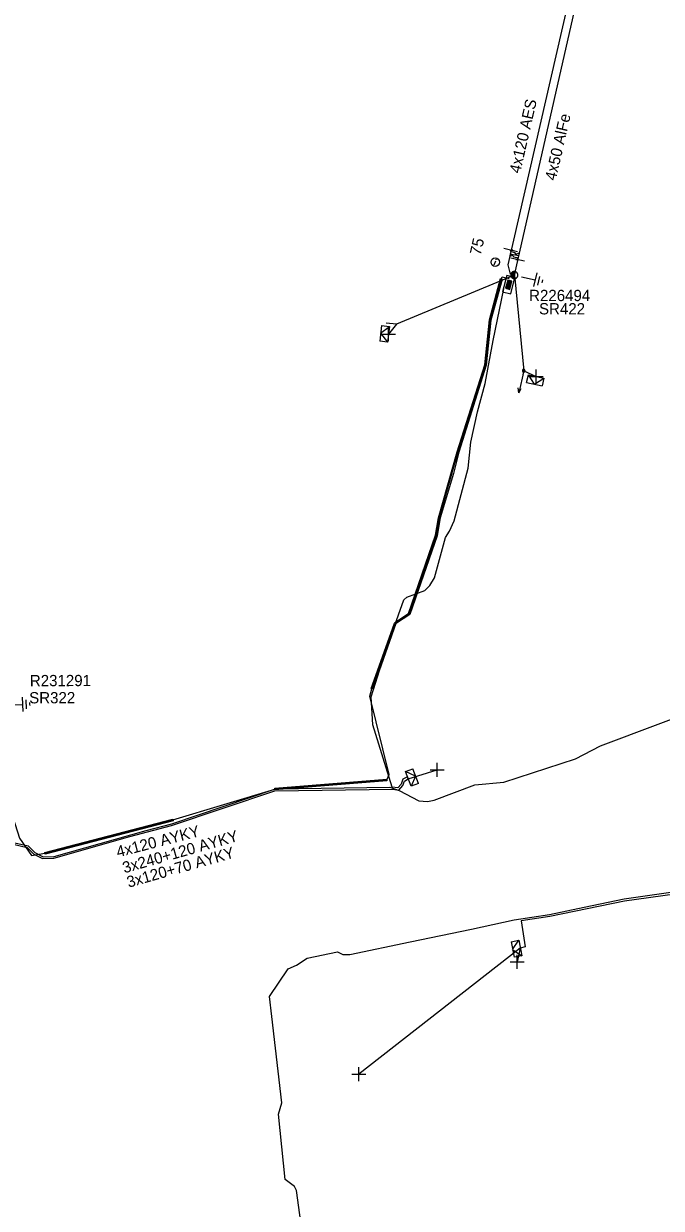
# Model space of a CAD drawing. Extents: x -544780 to -541582, y -1198995 to -1196551.
# Drawn here: x -542649.1 to -542592.5, y -1198255 to -1198149.8 of the extents above; entities that cross this region are included whole.
import ezdxf

# ---------------------------------------------------------------- set-up
doc = ezdxf.new("R2010")
doc.units = 0
for name, color, linetype in [('Vrstva 1', 7, 'Continuous'), ('Vrstva 10', 7, 'Continuous'), ('Vrstva 13', 7, 'Continuous'), ('Vrstva 14', 7, 'Continuous'), ('Vrstva 15', 7, 'Continuous'), ('Vrstva 18', 7, 'Continuous'), ('Vrstva 2', 7, 'Continuous'), ('Vrstva 20', 7, 'Continuous'), ('Vrstva 28', 7, 'Continuous'), ('Vrstva 29', 7, 'Continuous'), ('Vrstva 30', 7, 'Continuous'), ('Vrstva 31', 7, 'Continuous'), ('Vrstva 34', 7, 'Continuous'), ('Vrstva 36', 7, 'Continuous'), ('Vrstva 5', 7, 'Continuous'), ('Vrstva 50', 7, 'Continuous'), ('Vrstva 51', 7, 'Continuous'), ('Vrstva 54', 7, 'Continuous'), ('Vrstva 59', 7, 'Continuous'), ('Vrstva 6', 7, 'Continuous'), ('Vrstva 8', 7, 'Continuous'), ('Vrstva 9', 7, 'Continuous')]:
    doc.layers.add(name, color=color, linetype=linetype)

# ---------------------------------------------------------------- blocks, each defined once
blk = doc.blocks.new('NN440')
at = {"layer": 'Vrstva 2'}
for points in [[(0.63, 0), (0.63, 0.06), (0.62, 0.13), (0.6, 0.19), (0.58, 0.25), (0.55, 0.31), (0.51, 0.37), (0.47, 0.42), (0.42, 0.46), (0.37, 0.51), (0.32, 0.54), (0.26, 0.57), (0.2, 0.59), (0.13, 0.61), (0.07, 0.62), (0, 0.63), (-0.06, 0.62), (-0.13, 0.61), (-0.19, 0.59), (-0.26, 0.57), (-0.31, 0.54), (-0.37, 0.51), (-0.42, 0.46), (-0.47, 0.42), (-0.51, 0.37), (-0.54, 0.31), (-0.57, 0.25), (-0.6, 0.19), (-0.62, 0.13), (-0.63, 0.06), (-0.63, 0), (-0.63, -0.07), (-0.62, -0.14), (-0.6, -0.2), (-0.57, -0.26), (-0.54, -0.32), (-0.51, -0.37), (-0.47, -0.43), (-0.42, -0.47), (-0.37, -0.51), (-0.31, -0.55), (-0.26, -0.58), (-0.19, -0.6), (-0.13, -0.62), (-0.06, -0.63), (0, -0.63), (0.07, -0.63), (0.13, -0.62), (0.2, -0.6), (0.26, -0.58), (0.32, -0.55), (0.37, -0.51), (0.42, -0.47), (0.47, -0.43), (0.51, -0.37), (0.55, -0.32), (0.58, -0.26), (0.6, -0.2), (0.62, -0.14), (0.63, -0.07), (0.63, 0)], [(-0.63, 0), (0.63, 0)], [(-0.6, -0.18), (0.57, -0.18)], [(-0.51, -0.32), (0.5, -0.32)], [(-0.37, -0.47), (0.35, -0.47)]]:
    blk.add_lwpolyline(points, dxfattribs=at)
blk = doc.blocks.new('NN560')
at = {"layer": 'Vrstva 2'}
for points in [[(2, 0), (1.59, 0.14)], [(0, 0), (2, 0)], [(2, 0), (1.59, -0.13)]]:
    blk.add_lwpolyline(points, dxfattribs=at)
blk = doc.blocks.new('NN840')
at = {"layer": 'Vrstva 15'}
for points in [[(0, 0.62), (0, -0.63)], [(-0.75, -0.71), (-0.75, -0.66)], [(-0.73, -0.76), (-0.75, -0.71)], [(-0.66, -0.8), (-0.73, -0.76)], [(-0.63, -0.8), (-0.66, -0.8)], [(-0.56, -0.76), (-0.63, -0.8)], [(-0.54, -0.71), (-0.56, -0.76)], [(-0.54, -0.38), (-0.54, -0.71)], [(-0.33, -0.38), (-0.33, -0.8)], [(-0.33, -0.64), (-0.13, -0.38)], [(-0.26, -0.56), (-0.09, -0.8)]]:
    blk.add_lwpolyline(points, dxfattribs=at)
blk = doc.blocks.new('NN770')
at = {"layer": 'Vrstva 10'}
for p, q in [((0, 0.19), (0, 0.26)), ((0, -0.28), (0, 0.11))]:
    blk.add_line(p, q, dxfattribs=at)
blk.add_circle((0, -0.01), 0.375, dxfattribs=at)
blk = doc.blocks.new('NN800')
at = {"layer": 'Vrstva 1'}
for points in [[(-0.44, 0.44), (0.44, -0.44)], [(-0.44, -0.44), (0.44, 0.44)]]:
    blk.add_lwpolyline(points, dxfattribs=at)
blk = doc.blocks.new('NN620')
at = {"layer": 'Vrstva 8'}
for points in [[(0.75, 0), (-0.75, 0)], [(-0.75, 0), (-0.75, -0.75)], [(0.75, -0.75), (0.75, 0)], [(-0.75, -0.75), (0.75, -0.75)], [(0.37, -0.18), (-0.38, -0.18)], [(-0.38, -0.18), (-0.38, -0.56)], [(-0.38, -0.56), (0.37, -0.56)], [(0.32, -0.23), (-0.33, -0.23)], [(-0.33, -0.23), (-0.33, -0.51)], [(-0.33, -0.51), (0.32, -0.51)], [(0.27, -0.27), (-0.28, -0.27)], [(-0.28, -0.27), (-0.28, -0.46)], [(-0.28, -0.46), (0.27, -0.46)], [(0.23, -0.32), (-0.23, -0.32)], [(-0.23, -0.32), (-0.23, -0.42)], [(-0.23, -0.42), (0.23, -0.42)], [(-0.19, -0.37), (0.19, -0.37)], [(0.23, -0.42), (0.23, -0.32)], [(0.27, -0.46), (0.27, -0.27)], [(0.32, -0.51), (0.32, -0.23)], [(0.37, -0.56), (0.37, -0.18)]]:
    blk.add_lwpolyline(points, dxfattribs=at)
blk = doc.blocks.new('NN630')
at = {"layer": 'Vrstva 9'}
for points in [[(0, -0.7), (-0.7, 0)], [(-0.7, -0.7), (-0.7, 0), (0.7, 0), (0.7, -0.7)], [(-0.7, -0.7), (0.7, -0.7)], [(0, -0.7), (0.7, 0)]]:
    blk.add_lwpolyline(points, dxfattribs=at)
blk = doc.blocks.new('NN810')
at = {"layer": 'Vrstva 14'}
for points in [[(0, -0.64), (0, -1.89)], [(0.63, -1.89), (-0.62, -1.89)], [(0.39, -2.2), (-0.4, -2.2)], [(0, -2.52), (-0.12, -2.52)], [(0.14, -2.52), (0, -2.52)]]:
    blk.add_lwpolyline(points, dxfattribs=at)
blk = doc.blocks.new('NN500')
at = {"layer": 'Vrstva 2'}
for points in [[(0, -0.24), (0.02, -0.23), (0.05, -0.23), (0.07, -0.22), (0.09, -0.22), (0.12, -0.2), (0.14, -0.19), (0.16, -0.18), (0.17, -0.16), (0.19, -0.14), (0.2, -0.12), (0.21, -0.1), (0.22, -0.07), (0.23, -0.05), (0.23, -0.02), (0.23, 0), (0.23, 0.02), (0.23, 0.05), (0.22, 0.07), (0.21, 0.1), (0.2, 0.12), (0.19, 0.14), (0.17, 0.16), (0.16, 0.17), (0.14, 0.19), (0.12, 0.2), (0.09, 0.21), (0.07, 0.22), (0.05, 0.23), (0.02, 0.23), (0, 0.23), (-0.03, 0.23), (-0.05, 0.23), (-0.07, 0.22), (-0.1, 0.21), (-0.12, 0.2), (-0.14, 0.19), (-0.16, 0.17), (-0.18, 0.16), (-0.19, 0.14), (-0.2, 0.12), (-0.22, 0.1), (-0.22, 0.07), (-0.23, 0.05), (-0.23, 0.02), (-0.24, 0), (-0.23, -0.02), (-0.23, -0.05), (-0.22, -0.07), (-0.22, -0.1), (-0.2, -0.12), (-0.19, -0.14), (-0.18, -0.16), (-0.16, -0.18), (-0.14, -0.19), (-0.12, -0.2), (-0.1, -0.22), (-0.07, -0.22), (-0.05, -0.23), (-0.03, -0.23), (0, -0.24)], [(0, -0.24), (0.02, -0.23), (0.05, -0.23), (0.07, -0.22), (0.09, -0.22), (0.12, -0.2), (0.14, -0.19), (0.16, -0.18), (0.17, -0.16), (0.19, -0.14), (0.2, -0.12), (0.21, -0.1), (0.22, -0.07), (0.23, -0.05), (0.23, -0.02), (0.23, 0), (0.23, 0.02), (0.23, 0.05), (0.22, 0.07), (0.21, 0.1), (0.2, 0.12), (0.19, 0.14), (0.17, 0.16), (0.16, 0.17), (0.14, 0.19), (0.12, 0.2), (0.09, 0.21), (0.07, 0.22), (0.05, 0.23), (0.02, 0.23), (0, 0.23), (-0.03, 0.23), (-0.05, 0.23), (-0.07, 0.22), (-0.1, 0.21), (-0.12, 0.2), (-0.14, 0.19), (-0.16, 0.17), (-0.18, 0.16), (-0.19, 0.14), (-0.2, 0.12), (-0.22, 0.1), (-0.22, 0.07), (-0.23, 0.05), (-0.23, 0.02), (-0.24, 0), (-0.23, -0.02), (-0.23, -0.05), (-0.22, -0.07), (-0.22, -0.1), (-0.2, -0.12), (-0.19, -0.14), (-0.18, -0.16), (-0.16, -0.18), (-0.14, -0.19), (-0.12, -0.2), (-0.1, -0.22), (-0.07, -0.22), (-0.05, -0.23), (-0.03, -0.23), (0, -0.24)], [(0, -0.21), (0.02, -0.2), (0.04, -0.2), (0.06, -0.2), (0.08, -0.19), (0.1, -0.18), (0.12, -0.17), (0.14, -0.15), (0.15, -0.14), (0.16, -0.12), (0.18, -0.1), (0.19, -0.08), (0.19, -0.06), (0.2, -0.04), (0.2, -0.02), (0.2, 0), (0.2, 0.02), (0.2, 0.04), (0.19, 0.06), (0.19, 0.08), (0.18, 0.1), (0.16, 0.12), (0.15, 0.14), (0.14, 0.15), (0.12, 0.17), (0.1, 0.18), (0.08, 0.19), (0.06, 0.19), (0.04, 0.2), (0.02, 0.2), (0, 0.2), (-0.02, 0.2), (-0.04, 0.2), (-0.06, 0.19), (-0.08, 0.19), (-0.1, 0.18), (-0.12, 0.17), (-0.14, 0.15), (-0.15, 0.14), (-0.17, 0.12), (-0.18, 0.1), (-0.19, 0.08), (-0.2, 0.06), (-0.2, 0.04), (-0.21, 0.02), (-0.21, 0), (-0.21, -0.02), (-0.2, -0.04), (-0.2, -0.06), (-0.19, -0.08), (-0.18, -0.1), (-0.17, -0.12), (-0.15, -0.14), (-0.14, -0.15), (-0.12, -0.17), (-0.1, -0.18), (-0.08, -0.19), (-0.06, -0.2), (-0.04, -0.2), (-0.02, -0.2), (0, -0.21)], [(0, -0.18), (0.02, -0.18), (0.04, -0.17), (0.05, -0.17), (0.07, -0.16), (0.09, -0.15), (0.1, -0.14), (0.12, -0.13), (0.13, -0.12), (0.14, -0.1), (0.15, -0.09), (0.16, -0.07), (0.17, -0.05), (0.17, -0.04), (0.17, -0.02), (0.17, 0), (0.17, 0.02), (0.17, 0.04), (0.17, 0.05), (0.16, 0.07), (0.15, 0.09), (0.14, 0.1), (0.13, 0.12), (0.12, 0.13), (0.1, 0.14), (0.09, 0.15), (0.07, 0.16), (0.05, 0.17), (0.04, 0.17), (0.02, 0.17), (0, 0.18), (-0.02, 0.17), (-0.04, 0.17), (-0.06, 0.17), (-0.07, 0.16), (-0.09, 0.15), (-0.1, 0.14), (-0.12, 0.13), (-0.13, 0.12), (-0.14, 0.1), (-0.15, 0.09), (-0.16, 0.07), (-0.17, 0.05), (-0.17, 0.04), (-0.18, 0.02), (-0.18, 0), (-0.18, -0.02), (-0.17, -0.04), (-0.17, -0.05), (-0.16, -0.07), (-0.15, -0.09), (-0.14, -0.1), (-0.13, -0.12), (-0.12, -0.13), (-0.1, -0.14), (-0.09, -0.15), (-0.07, -0.16), (-0.06, -0.17), (-0.04, -0.17), (-0.02, -0.18), (0, -0.18)], [(0, -0.15), (0.01, -0.15), (0.03, -0.14), (0.04, -0.14), (0.06, -0.13), (0.07, -0.13), (0.08, -0.12), (0.1, -0.11), (0.11, -0.1), (0.12, -0.09), (0.13, -0.07), (0.13, -0.06), (0.14, -0.05), (0.14, -0.03), (0.14, -0.02), (0.14, 0), (0.14, 0.01), (0.14, 0.03), (0.14, 0.04), (0.13, 0.06), (0.13, 0.07), (0.12, 0.09), (0.11, 0.1), (0.1, 0.11), (0.08, 0.12), (0.07, 0.13), (0.06, 0.13), (0.04, 0.14), (0.03, 0.14), (0.01, 0.14), (0, 0.15), (-0.02, 0.14), (-0.03, 0.14), (-0.05, 0.14), (-0.06, 0.13), (-0.07, 0.13), (-0.09, 0.12), (-0.1, 0.11), (-0.11, 0.1), (-0.12, 0.09), (-0.13, 0.07), (-0.13, 0.06), (-0.14, 0.04), (-0.14, 0.03), (-0.15, 0.01), (-0.15, 0), (-0.15, -0.02), (-0.14, -0.03), (-0.14, -0.05), (-0.13, -0.06), (-0.13, -0.07), (-0.12, -0.09), (-0.11, -0.1), (-0.1, -0.11), (-0.09, -0.12), (-0.07, -0.13), (-0.06, -0.13), (-0.05, -0.14), (-0.03, -0.14), (-0.02, -0.15), (0, -0.15)], [(0, -0.12), (0.01, -0.12), (0.02, -0.11), (0.03, -0.11), (0.05, -0.11), (0.06, -0.1), (0.07, -0.09), (0.08, -0.09), (0.09, -0.08), (0.09, -0.07), (0.1, -0.06), (0.11, -0.05), (0.11, -0.04), (0.11, -0.02), (0.11, -0.01), (0.12, 0), (0.11, 0.01), (0.11, 0.02), (0.11, 0.04), (0.11, 0.05), (0.1, 0.06), (0.09, 0.07), (0.09, 0.08), (0.08, 0.09), (0.07, 0.09), (0.06, 0.1), (0.05, 0.11), (0.03, 0.11), (0.02, 0.11), (0.01, 0.12), (0, 0.12), (-0.01, 0.12), (-0.03, 0.11), (-0.04, 0.11), (-0.05, 0.11), (-0.06, 0.1), (-0.07, 0.09), (-0.08, 0.09), (-0.09, 0.08), (-0.1, 0.07), (-0.1, 0.06), (-0.11, 0.05), (-0.11, 0.04), (-0.12, 0.02), (-0.12, 0.01), (-0.12, 0), (-0.12, -0.01), (-0.12, -0.02), (-0.11, -0.04), (-0.11, -0.05), (-0.1, -0.06), (-0.1, -0.07), (-0.09, -0.08), (-0.08, -0.09), (-0.07, -0.09), (-0.06, -0.1), (-0.05, -0.11), (-0.04, -0.11), (-0.03, -0.11), (-0.01, -0.12), (0, -0.12)], [(0, -0.09), (0.01, -0.09), (0.02, -0.09), (0.03, -0.08), (0.03, -0.08), (0.04, -0.08), (0.05, -0.07), (0.06, -0.07), (0.06, -0.06), (0.07, -0.05), (0.07, -0.04), (0.08, -0.04), (0.08, -0.03), (0.08, -0.02), (0.09, -0.01), (0.09, 0), (0.09, 0.01), (0.08, 0.02), (0.08, 0.03), (0.08, 0.03), (0.07, 0.04), (0.07, 0.05), (0.06, 0.06), (0.06, 0.06), (0.05, 0.07), (0.04, 0.07), (0.03, 0.08), (0.03, 0.08), (0.02, 0.08), (0.01, 0.09), (0, 0.09), (-0.01, 0.09), (-0.02, 0.08), (-0.03, 0.08), (-0.04, 0.08), (-0.04, 0.07), (-0.05, 0.07), (-0.06, 0.06), (-0.07, 0.06), (-0.07, 0.05), (-0.08, 0.04), (-0.08, 0.03), (-0.08, 0.03), (-0.09, 0.02), (-0.09, 0.01), (-0.09, 0), (-0.09, -0.01), (-0.09, -0.02), (-0.08, -0.03), (-0.08, -0.04), (-0.08, -0.04), (-0.07, -0.05), (-0.07, -0.06), (-0.06, -0.07), (-0.05, -0.07), (-0.04, -0.08), (-0.04, -0.08), (-0.03, -0.08), (-0.02, -0.09), (-0.01, -0.09), (0, -0.09)], [(0, -0.06), (0, -0.06), (0.01, -0.06), (0.02, -0.05), (0.02, -0.05), (0.03, -0.05), (0.03, -0.05), (0.04, -0.04), (0.04, -0.04), (0.05, -0.03), (0.05, -0.03), (0.05, -0.02), (0.05, -0.02), (0.05, -0.01), (0.06, -0.01), (0.06, 0), (0.06, 0.01), (0.05, 0.01), (0.05, 0.02), (0.05, 0.02), (0.05, 0.03), (0.05, 0.03), (0.04, 0.04), (0.04, 0.04), (0.03, 0.05), (0.03, 0.05), (0.02, 0.05), (0.02, 0.05), (0.01, 0.06), (0, 0.06), (0, 0.06), (-0.01, 0.06), (-0.01, 0.06), (-0.02, 0.05), (-0.02, 0.05), (-0.03, 0.05), (-0.03, 0.05), (-0.04, 0.04), (-0.04, 0.04), (-0.05, 0.03), (-0.05, 0.03), (-0.05, 0.02), (-0.06, 0.02), (-0.06, 0.01), (-0.06, 0.01), (-0.06, 0), (-0.06, -0.01), (-0.06, -0.01), (-0.06, -0.02), (-0.05, -0.02), (-0.05, -0.03), (-0.05, -0.03), (-0.04, -0.04), (-0.04, -0.04), (-0.03, -0.05), (-0.03, -0.05), (-0.02, -0.05), (-0.02, -0.05), (-0.01, -0.06), (-0.01, -0.06), (0, -0.06)], [(0, -0.03), (0, -0.03), (0, -0.03), (0.01, -0.03), (0.01, -0.03), (0.01, -0.02), (0.02, -0.02), (0.02, -0.02), (0.02, -0.02), (0.02, -0.02), (0.02, -0.01), (0.02, -0.01), (0.03, -0.01), (0.03, -0.01), (0.03, 0), (0.03, 0), (0.03, 0), (0.03, 0.01), (0.03, 0.01), (0.02, 0.01), (0.02, 0.01), (0.02, 0.02), (0.02, 0.02), (0.02, 0.02), (0.02, 0.02), (0.01, 0.02), (0.01, 0.02), (0.01, 0.03), (0, 0.03), (0, 0.03), (0, 0.03), (0, 0.03), (-0.01, 0.03), (-0.01, 0.03), (-0.01, 0.02), (-0.02, 0.02), (-0.02, 0.02), (-0.02, 0.02), (-0.02, 0.02), (-0.02, 0.02), (-0.03, 0.01), (-0.03, 0.01), (-0.03, 0.01), (-0.03, 0.01), (-0.03, 0), (-0.03, 0), (-0.03, 0), (-0.03, -0.01), (-0.03, -0.01), (-0.03, -0.01), (-0.03, -0.01), (-0.02, -0.02), (-0.02, -0.02), (-0.02, -0.02), (-0.02, -0.02), (-0.02, -0.02), (-0.01, -0.03), (-0.01, -0.03), (-0.01, -0.03), (0, -0.03), (0, -0.03)], [(0.23, 0), (0.7, 0)]]:
    blk.add_lwpolyline(points, dxfattribs=at)
blk = doc.blocks.new('NN510')
at = {"layer": 'Vrstva 2'}
blk.add_lwpolyline([(0, 0), (0, 0.94)], dxfattribs=at)

msp = doc.modelspace()

# ---------------------------------------------------------------- linework, layer by layer
at = {"layer": 'Vrstva 1'}
msp.add_lwpolyline([(-542605.57, -1198172.11), (-542600.19, -1198148.54), (-542596.36, -1198125.3)], dxfattribs=at)
at = {"layer": 'Vrstva 20'}
for points in [[(-542614.97, -1198202.15), (-542612.56, -1198195.21), (-542612.31, -1198193.66), (-542610.64, -1198187.79), (-542608.2, -1198180.09), (-542607.79, -1198176.08), (-542606.79, -1198172.4), (-542606.64, -1198172.49), (-542607.65, -1198176.1), (-542608.06, -1198180.11), (-542610.5, -1198187.83), (-542610.97, -1198189.71), (-542612.15, -1198193.67), (-542612.42, -1198195.25), (-542614.85, -1198202.24), (-542616.12, -1198203.08), (-542616.2, -1198202.96)], [(-542618.15, -1198208.85), (-542618.29, -1198208.81), (-542616.23, -1198203), (-542616.09, -1198203.04)], [(-542626.83, -1198217.8), (-542626.84, -1198217.66), (-542616.91, -1198216.86), (-542616.9, -1198217)], [(-542647.24, -1198223.5), (-542647.28, -1198223.36), (-542635.91, -1198220.41), (-542635.87, -1198220.55)]]:
    msp.add_lwpolyline(points, close=True, dxfattribs=at)
at = {"layer": 'Vrstva 5'}
for points in [[(-542650.6, -1198210.3), (-542650.61, -1198210.71), (-542652.88, -1198210.88), (-542651.64, -1198215.47), (-542649.51, -1198222.1), (-542648.46, -1198223.62), (-542647.26, -1198223.43), (-542635.89, -1198220.48), (-542626.84, -1198217.73), (-542616.9, -1198216.93), (-542616.69, -1198216.44), (-542618.41, -1198209.49), (-542618.22, -1198208.83), (-542616.16, -1198203.02), (-542614.91, -1198202.19), (-542612.49, -1198195.23), (-542612.24, -1198193.67), (-542610.57, -1198187.81), (-542608.13, -1198180.1), (-542607.72, -1198176.09), (-542606.66, -1198172.27), (-542606.02, -1198172.42)], [(-542650.08, -1198222.64), (-542648.84, -1198222.93), (-542648.26, -1198223.5), (-542647.48, -1198223.89), (-542646.46, -1198223.87), (-542639.72, -1198221.95), (-542636.01, -1198220.98), (-542626.83, -1198217.89), (-542616.35, -1198217.74), (-542615.84, -1198217.82), (-542615.49, -1198217.41), (-542615.34, -1198217.02), (-542615, -1198216.84), (-542615.07, -1198216.66), (-542615.47, -1198216.86), (-542615.63, -1198217.29), (-542615.91, -1198217.64), (-542616.43, -1198217.56), (-542618.13, -1198212.03), (-542618.3, -1198209.56), (-542616.95, -1198205.34), (-542615.4, -1198200.95), (-542615.11, -1198200.69), (-542613.52, -1198200.1), (-542613.08, -1198199.66), (-542612.66, -1198198.98), (-542611.69, -1198195.4), (-542611.34, -1198194.84), (-542610.91, -1198193.93), (-542609.66, -1198189.24), (-542609.44, -1198186.94), (-542608.84, -1198184.25), (-542608.17, -1198181.73), (-542607.45, -1198177.92), (-542606.5, -1198173.33)], [(-542649.93, -1198222.52), (-542648.74, -1198222.78), (-542648.16, -1198223.38), (-542647.43, -1198223.76), (-542646.43, -1198223.72), (-542638.27, -1198221.4), (-542635.98, -1198220.82), (-542626.78, -1198217.71), (-542616.64, -1198217.57), (-542615.8, -1198217.87), (-542614.05, -1198218.79), (-542613.27, -1198218.83), (-542612.69, -1198218.71), (-542609.09, -1198217.36), (-542606.52, -1198217.11), (-542600.14, -1198215.04), (-542597.92, -1198213.9), (-542587.91, -1198210.13)], [(-542578.09, -1198214.3), (-542577.45, -1198214.6), (-542578.3, -1198226.2), (-542578.54, -1198228.04), (-542578.69, -1198228.13), (-542578.83, -1198227.98), (-542578.68, -1198226.47), (-542579.41, -1198226.61), (-542579.99, -1198226.91), (-542584.4, -1198226.92), (-542585.27, -1198226.38), (-542586.86, -1198226.44), (-542595.78, -1198227.68), (-542602.42, -1198229.06), (-542604.96, -1198229.44), (-542604.6, -1198231.75), (-542605.04, -1198231.85)], [(-542624.02, -1198259.84), (-542624.91, -1198253.38), (-542625.1, -1198253.01), (-542625.92, -1198252.38), (-542626.53, -1198246.6), (-542626.22, -1198245.59), (-542627.12, -1198237.91), (-542627.33, -1198236.15), (-542625.65, -1198233.7), (-542624.91, -1198233.36), (-542623.96, -1198232.76), (-542621.28, -1198232.17), (-542620.81, -1198232.42), (-542620.17, -1198232.41), (-542614.82, -1198231.29), (-542609.38, -1198230.17), (-542605.58, -1198229.33), (-542602.45, -1198228.86), (-542599.36, -1198228.22), (-542595.82, -1198227.49), (-542589.2, -1198226.54)]]:
    msp.add_lwpolyline(points, dxfattribs=at)
at = {"layer": 'Vrstva 50'}
msp.add_lwpolyline([(-542605.92, -1198172.02), (-542606.12, -1198171.21), (-542600.86, -1198148.27), (-542597.1, -1198125.47), (-542602.99, -1198090.91), (-542611.79, -1198069.81), (-542610.86, -1198069), (-542610.92, -1198068.76)], dxfattribs=at)
at = {"layer": 'Vrstva 54'}
msp.add_lwpolyline([(-542605.57, -1198172.11), (-542616.03, -1198176.48), (-542616.75, -1198177.36)], dxfattribs=at)
at = {"layer": 'Vrstva 59'}
for points in [[(-542615, -1198216.84), (-542612.42, -1198216.02)], [(-542605.04, -1198231.85), (-542619.38, -1198243.05)], [(-542605.04, -1198231.85), (-542605.31, -1198233.07)]]:
    msp.add_lwpolyline(points, dxfattribs=at)
at = {"layer": 'Vrstva 8'}
msp.add_lwpolyline([(-542605.57, -1198172.11), (-542604.74, -1198180.6), (-542603.64, -1198181.11)], dxfattribs=at)

# ---------------------------------------------------------------- block references
at = {"layer": 'Vrstva 13', "yscale": 0.5}
for name, p, xscale, rotation in [('NN440', (-542605.57, -1198172.11), 0.5000000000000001, -102.92464447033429), ('NN500', (-542604.74, -1198180.6), 0.5, -102.78000003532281)]:
    msp.add_blockref(name, p, dxfattribs=dict(at, xscale=xscale, rotation=rotation))
at = {"layer": 'Vrstva 13'}
for name, p, rotation in [('NN510', (-542616.03, -1198176.48), 83.41331663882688), ('NN560', (-542604.74, -1198180.6), -102.77988613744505)]:
    msp.add_blockref(name, p, dxfattribs=dict(at, rotation=rotation))
at = {"layer": 'Vrstva 15'}
for p, rotation in [((-542605.57, -1198172.11), 77.0534917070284), ((-542651.14, -1198210.3), 92.50742329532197)]:
    msp.add_blockref('NN810', p, dxfattribs=dict(at, rotation=rotation))
at = {"layer": 'Vrstva 18'}
for p, rotation in [((-542605.91, -1198169.87), 77.09041660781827), ((-542605.26, -1198170.74), -102.85796391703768)]:
    msp.add_blockref('NN840', p, dxfattribs=dict(at, rotation=rotation))
at = {"layer": 'Vrstva 28', "rotation": 75.62840830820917}
msp.add_blockref('NN620', (-542606.43, -1198172.87), dxfattribs=at)
at = {"layer": 'Vrstva 31'}
for p, rotation in [((-542616.75, -1198177.36), -96.58668329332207), ((-542603.64, -1198181.11), -12.779886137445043), ((-542615, -1198216.84), 111.09445280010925), ((-542605.04, -1198231.85), -78.99344725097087)]:
    msp.add_blockref('NN630', p, dxfattribs=dict(at, rotation=rotation))
at = {"layer": 'Vrstva 34'}
for p, rotation in [((-542616.75, -1198177.36), 44.99999995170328), ((-542603.64, -1198181.11), 44.99999995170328), ((-542612.42, -1198216.02), 45), ((-542605.31, -1198233.08), 45.00000009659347), ((-542619.38, -1198243.05), 45)]:
    msp.add_blockref('NN800', p, dxfattribs=dict(at, rotation=rotation))
at = {"layer": 'Vrstva 36', "rotation": -18.70401939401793}
msp.add_blockref('NN770', (-542607.26, -1198170.95), dxfattribs=at)

# ---------------------------------------------------------------- texts
at = {"layer": 'Vrstva 14'}
msp.add_text('75', height=1, rotation=77.075, dxfattribs=at).set_placement((-542608.57, -1198170.41))
at = {"layer": 'Vrstva 2'}
msp.add_text('4x50 AlFe', height=1, rotation=77.142, dxfattribs=at).set_placement((-542601.9, -1198163.78))
at = {"layer": 'Vrstva 29'}
msp.add_text('R226494', height=1, dxfattribs=at).set_placement((-542604.26, -1198174.42))
msp.add_text('R231291', height=1, rotation=0.137, dxfattribs=at).set_placement((-542648.6, -1198208.61))
at = {"layer": 'Vrstva 30'}
msp.add_text('SR422', height=1, dxfattribs=at).set_placement((-542603.38, -1198175.6))
msp.add_text('SR322', height=1, rotation=0.137, dxfattribs=at).set_placement((-542648.66, -1198210.13))
at = {"layer": 'Vrstva 51'}
msp.add_text('4x120 AES', height=1, rotation=77.09, dxfattribs=at).set_placement((-542605.06, -1198163.14))
at = {"layer": 'Vrstva 6'}
for s, rotation, p in [('4x120 AYKY', 14.545, (-542640.78, -1198223.81)), ('3x240+120 AYKY', 15.845, (-542640.21, -1198225.22)), ('3x120+70 AYKY', 15.899, (-542639.83, -1198226.5))]:
    msp.add_text(s, height=1, rotation=rotation, dxfattribs=at).set_placement(p)

doc.saveas('drawing.dxf')
